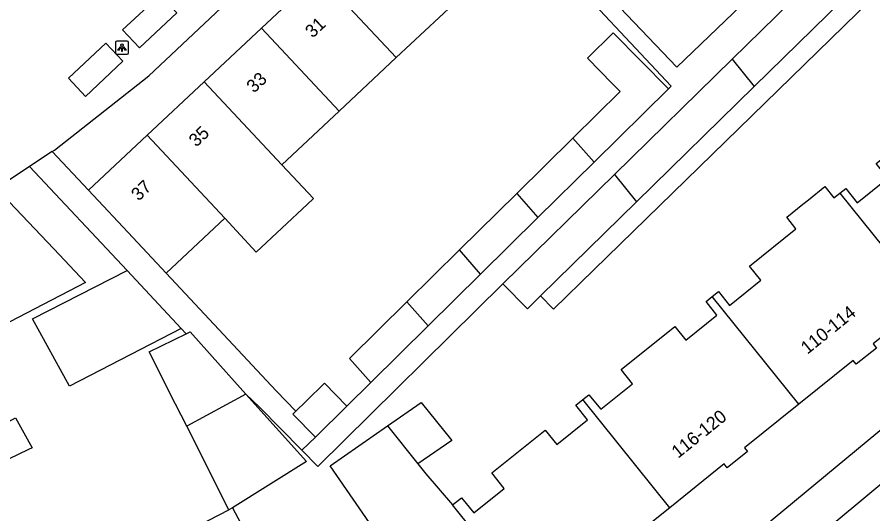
# Model space of a CAD drawing. Extents: x 161882 to 162509, y 381687 to 382379.
# Drawn here: x 162344.1 to 162409.8, y 381753.6 to 381791.7 of the extents above; entities that cross this region are included whole.
import ezdxf

# ---------------------------------------------------------------- set-up
doc = ezdxf.new("R2010")
doc.units = 0
for name, color, linetype in [('IMGEO_Lichtpunt', 7, 'Continuous'), ('IMGEO_Pand', 7, 'Continuous'), ('IMGEO_Pand_nummerreeks', 7, 'Continuous'), ('IMGEO_Rijbaan_lokaal_open', 7, 'Continuous'), ('IMGEO_Voetpad_open', 7, 'Continuous')]:
    doc.layers.add(name, color=color, linetype=linetype)

msp = doc.modelspace()

# ---------------------------------------------------------------- linework, layer by layer
at = {"layer": 'IMGEO_Lichtpunt'}
for p, q in [((162351.641, 381789.796), (162351.641, 381788.989)), ((162351.641, 381789.796), (162351.641, 381788.989)), ((162352.543, 381789.891), (162351.735, 381789.891)), ((162352.543, 381789.891), (162351.735, 381789.891)), ((162352.637, 381788.989), (162352.637, 381789.796)), ((162352.637, 381788.989), (162352.637, 381789.796)), ((162351.735, 381788.895), (162352.543, 381788.895)), ((162351.735, 381788.895), (162352.543, 381788.895))]:
    msp.add_line(p, q, dxfattribs=at)
for points in [[(162352.015, 381789.46), (162352.054, 381789.432), (162351.866, 381789.17), (162351.828, 381789.197), (162352.015, 381789.46)], [(162352.117, 381789.412), (162352.164, 381789.412), (162352.164, 381789.09), (162352.117, 381789.09), (162352.117, 381789.412)], [(162352.227, 381789.432), (162352.265, 381789.459), (162352.452, 381789.197), (162352.413, 381789.169), (162352.227, 381789.432)]]:
    msp.add_lwpolyline(points, dxfattribs=at)
msp.add_circle((162352.14, 381789.594), 0.0994, dxfattribs=at)
for centre, start, end in [((162351.735, 381789.796), 90, 180), ((162351.735, 381789.796), 90, 180), ((162352.543, 381789.796), 0, 90), ((162352.543, 381789.796), 0, 90), ((162351.735, 381788.989), 180, 270), ((162351.735, 381788.989), 180, 270), ((162352.543, 381788.989), 270, 0), ((162352.543, 381788.989), 270, 360)]:
    msp.add_arc(centre, 0.0946, start, end, dxfattribs=at)
at = {"layer": 'IMGEO_Pand'}
for points in [[(162399.042, 381788.517), (162408.087, 381797.371)], [(162367.248, 381795.01), (162362.853, 381790.895)], [(162367.248, 381795.01), (162373.224, 381788.631)], [(162402.22, 381795.039), (162394.777, 381787.903), (162390.397, 381792.472), (162390.786, 381792.845)], [(162409.777, 381795.269), (162400.732, 381786.414)], [(162377.619, 381792.746), (162373.224, 381788.631)], [(162362.853, 381790.895), (162358.459, 381786.781)], [(162368.83, 381784.517), (162362.853, 381790.895)], [(162386.785, 381782.445), (162390.429, 381786.038), (162389.849, 381786.627), (162387.914, 381788.589), (162389.897, 381790.545), (162394.14, 381786.241)], [(162373.224, 381788.631), (162368.83, 381784.517)], [(162389.981, 381779.647), (162399.042, 381788.517)], [(162399.042, 381788.517), (162400.732, 381786.414)], [(162358.459, 381786.781), (162354.064, 381782.667)], [(162358.459, 381786.781), (162364.435, 381780.403)], [(162400.732, 381786.414), (162391.671, 381777.544)], [(162394.14, 381786.241), (162388.42, 381780.6)], [(162407.314, 381778.223), (162407.768, 381778.588), (162408.653, 381777.486), (162411.003, 381779.373), (162410.105, 381780.491), (162414.302, 381783.861), (162415.174, 381782.775), (162417.505, 381784.647), (162416.639, 381785.725), (162417.13, 381786.119)], [(162368.83, 381784.517), (162364.435, 381780.403)], [(162354.064, 381782.667), (162349.562, 381778.452)], [(162360.041, 381776.288), (162354.064, 381782.667)], [(162382.473, 381778.193), (162386.785, 381782.445)], [(162386.785, 381782.445), (162388.42, 381780.6)], [(162364.435, 381780.403), (162366.852, 381777.807), (162366.391, 381777.376), (162362.458, 381773.692), (162360.041, 381776.288)], [(162388.42, 381780.6), (162384.104, 381776.345)], [(162381.418, 381771.264), (162389.981, 381779.647)], [(162389.981, 381779.647), (162391.671, 381777.544)], [(162355.536, 381772.071), (162352.98, 381774.802), (162349.562, 381778.452)], [(162397.503, 381770.285), (162397.973, 381770.662), (162398.827, 381769.599), (162401.234, 381771.531), (162400.36, 381772.619), (162403.933, 381775.489), (162403.224, 381776.372), (162404.457, 381777.362), (162404.899, 381777.718), (162406.154, 381778.726), (162406.855, 381777.854), (162407.314, 381778.223)], [(162378.082, 381773.863), (162382.473, 381778.193)], [(162382.473, 381778.193), (162384.104, 381776.345)], [(162407.314, 381778.223), (162413.962, 381769.95)], [(162340.852, 381776.203), (162343.461, 381777.564), (162346.9, 381773.934), (162349.34, 381771.36), (162327.927, 381760.251), (162323.187, 381758.657), (162323.025, 381759.138), (162315.359, 381756.62)], [(162391.671, 381777.544), (162384.304, 381770.332)], [(162360.041, 381776.288), (162355.536, 381772.071)], [(162384.104, 381776.345), (162379.695, 381771.996)], [(162374.022, 381769.859), (162378.082, 381773.863)], [(162379.695, 381771.996), (162378.082, 381773.863)], [(162356.7, 381767.828), (162348.117, 381763.384), (162345.256, 381768.578), (162352.533, 381772.272)], [(162352.533, 381772.272), (162356.7, 381767.828)], [(162379.695, 381771.996), (162375.677, 381768.034)], [(162384.304, 381770.332), (162383.296, 381769.345), (162381.418, 381771.264)], [(162371.265, 381763.684), (162369.629, 381765.527), (162374.022, 381769.859)], [(162374.022, 381769.859), (162375.677, 381768.034)], [(162387.561, 381762.363), (162388.029, 381762.739), (162388.931, 381761.615), (162391.38, 381763.581), (162390.507, 381764.668), (162394.626, 381767.976), (162395.468, 381766.928), (162397.869, 381768.855), (162397.027, 381769.903), (162397.503, 381770.285)], [(162404.147, 381762.016), (162397.503, 381770.285)], [(162413.962, 381769.95), (162409.859, 381766.656), (162410.127, 381766.323), (162408.569, 381765.072), (162408.327, 381765.372), (162404.147, 381762.016)], [(162375.677, 381768.034), (162371.265, 381763.684)], [(162357.113, 381760.311), (162356.254, 381762.016), (162354.236, 381766.022), (162357.084, 381767.419)], [(162357.084, 381767.419), (162357.375, 381767.562), (162360.358, 381764.241), (162361.669, 381762.781)], [(162365.51, 381761.465), (162366.295, 381762.239), (162367.697, 381763.622), (162369.425, 381761.869)], [(162361.669, 381762.781), (162357.113, 381760.311)], [(162361.669, 381762.781), (162366.323, 381757.6), (162360.635, 381754.053)], [(162372.542, 381760.336), (162375.144, 381762.136), (162377.48, 381759.226), (162374.878, 381757.426)], [(162377.539, 381754.267), (162378.231, 381754.823), (162379.168, 381753.657), (162381.517, 381755.543), (162380.562, 381756.732), (162384.662, 381760.024), (162385.553, 381758.916), (162387.913, 381760.811), (162387.017, 381761.926), (162387.561, 381762.363)], [(162394.235, 381754.059), (162387.561, 381762.363)], [(162404.147, 381762.016), (162399.97, 381758.662), (162400.207, 381758.367), (162398.654, 381757.121), (162398.417, 381757.417), (162394.235, 381754.059)], [(162365.51, 381761.465), (162365.275, 381761.233), (162367.003, 381759.48)], [(162369.425, 381761.869), (162367.003, 381759.48)], [(162335.338, 381756.311), (162335.574, 381756.413), (162343.96, 381760.963), (162345.233, 381758.654), (162344.953, 381758.52), (162342.647, 381757.423), (162341.585, 381756.918), (162339.815, 381756.076), (162339.078, 381755.776), (162339.481, 381754.784), (162336.59, 381753.609), (162336.966, 381752.684), (162332.122, 381750.715), (162331.746, 381751.641), (162330.831, 381751.268), (162331.346, 381750), (162331.984, 381748.43), (162328.432, 381746.987), (162325.192, 381745.671), (162320.559, 381743.788)], [(162360.342, 381753.901), (162357.113, 381760.311)], [(162366.899, 381744.958), (162373.521, 381749.484), (162373.164, 381750), (162368.13, 381757.284), (162372.542, 381760.336)], [(162372.542, 381760.336), (162374.878, 381757.426)], [(162374.878, 381757.426), (162375.487, 381756.667), (162377.539, 381754.267)], [(162360.635, 381754.053), (162363.375, 381748.9), (162359.18, 381746.721), (162356.49, 381751.901), (162360.342, 381753.901)], [(162360.635, 381754.053), (162360.342, 381753.901)], [(162380.965, 381750), (162377.539, 381754.267)], [(162394.235, 381754.059), (162390.053, 381750.701), (162390.283, 381750.415), (162389.766, 381750), (162388.764, 381749.195), (162388.539, 381749.476), (162384.189, 381745.983), (162380.965, 381750)]]:
    msp.add_lwpolyline(points, dxfattribs=at)
at = {"layer": 'IMGEO_Rijbaan_lokaal_open'}
for points in [[(162346.786, 381781.417), (162346.948, 381781.525), (162354.206, 381787.221), (162373.886, 381805.743)], [(162355.062, 381793.467), (162356.367, 381792.08), (162353.495, 381789.378), (162352.19, 381790.765), (162355.062, 381793.467)], [(162350.901, 381789.744), (162352.207, 381788.356), (162349.335, 381785.655), (162348.03, 381787.042), (162350.901, 381789.744)], [(162346.786, 381781.417), (162345.044, 381780.258)], [(162345.044, 381780.258), (162340.347, 381777.133)]]:
    msp.add_lwpolyline(points, dxfattribs=at)
at = {"layer": 'IMGEO_Voetpad_open'}
for points in [[(162427.183, 381794.183), (162419.997, 381803.132), (162406.611, 381790.087), (162388.399, 381772.337), (162385.299, 381769.316), (162384.304, 381770.332)], [(162382.12, 381796.96), (162382.932, 381796.092), (162385.347, 381796.033), (162394.352, 381786.45), (162394.14, 381786.241)], [(162342.256, 381716.825), (162343.866, 381713.286), (162356.915, 381719.329), (162365.839, 381723.151), (162398.308, 381750), (162437.038, 381782.026)], [(162349.562, 381778.452), (162346.786, 381781.417)], [(162352.533, 381772.272), (162345.044, 381780.258)], [(162355.536, 381772.071), (162363.995, 381763.033), (162365.51, 381761.465)], [(162381.418, 381771.264), (162367.187, 381757.231), (162365.972, 381758.464)], [(162357.084, 381767.419), (162356.7, 381767.828)], [(162371.265, 381763.684), (162369.425, 381761.869)], [(162365.972, 381758.464), (162362.713, 381761.769), (162361.669, 381762.781)], [(162367.003, 381759.48), (162365.972, 381758.464)], [(162405.024, 381751.353), (162411.161, 381756.457)]]:
    msp.add_lwpolyline(points, dxfattribs=at)

# ---------------------------------------------------------------- texts
at = {"layer": 'IMGEO_Pand_nummerreeks'}
for s, rotation, p in [('31', 43.11394, (162366.79, 381790.089)), ('33', 43.11394, (162362.278, 381785.862)), ('35', 43.11507, (162357.846, 381781.714)), ('37', 43.11394, (162353.416, 381777.566)), ('110-114', 38.94967, (162404.817, 381765.798)), ('116-120', 38.75554, (162394.878, 381757.807))]:
    msp.add_text(s, height=1, rotation=rotation, dxfattribs=at).set_placement(p)

doc.saveas('drawing.dxf')
